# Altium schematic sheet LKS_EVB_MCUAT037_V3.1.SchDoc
size 203 x 203 mm; DocumentNumber: 1; SheetNumber: 1; SheetTotal: 1
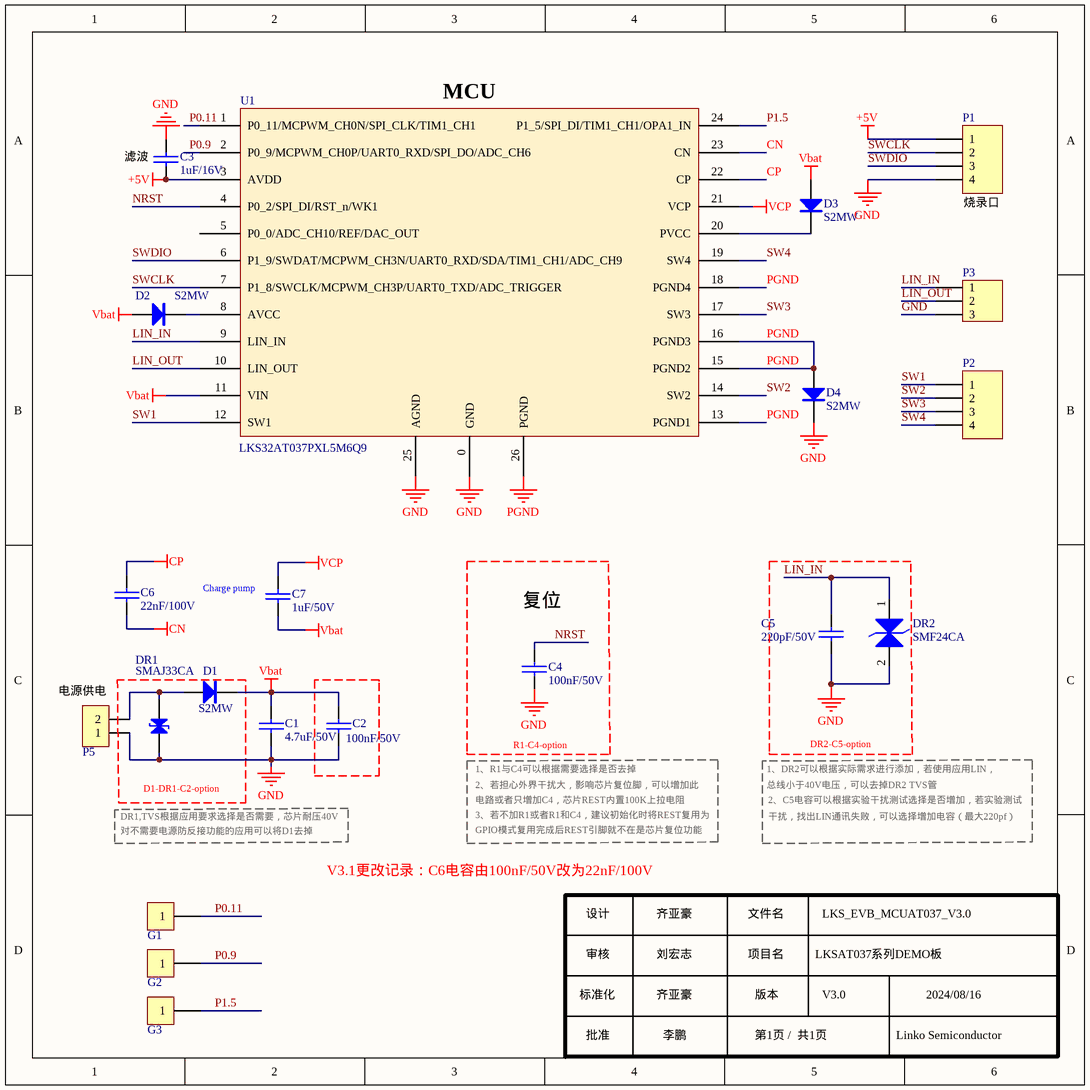
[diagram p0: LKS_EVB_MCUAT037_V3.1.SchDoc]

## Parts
C1  4.7uF/50V  [0805C]
C2  100nF/50V  [0603C]
C3  1uF/16V  [0603C]
C4  100nF/50V  [0603C]
C5  220pF/50V  [0603C]
C6  22nF/100V  [0603C]
C7  1uF/50V  [0603C]
D1  S2MW  [SOD-123]
D2  S2MW  [SOD-123]
D3  S2MW  [SOD-123]
D4  S2MW  [SOD-123]
DR1  SMAJ33CA  [SMB]
DR2  SMF24CA  [SOD-123F]
G1  PAD1.2  [TP-40]  (value not drawn)
G2  PAD1.2  [TP-40]  (value not drawn)
G3  PAD1.2  [TP-40]  (value not drawn)
P1  Header 4  [HDR 1X4]  (value not drawn)
P2  HDR-1X4  [HDR 1X4]  (value not drawn)
P3  1X3  [HDR 1X3]  (value not drawn)
P5  B2P-VH(LF)(SN)  [HDR 1X2]  (value not drawn)
U1  LKS32AT037PXL5M6Q9  [QFN24-0.55mm]

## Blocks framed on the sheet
复位: C4

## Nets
+5V: C3.2 P1.1 U1.3(AVDD)
CN: C6.2 U1.23(CN)
CP: C6.1 U1.22(CP)
GND: C1.2 C2.2 C3.1 C4.2 C5.2 D4.2(K) DR1.2(K) DR2.2(K) P1.4 P3.3 P5.1 U1.0(GND) U1.25(AGND)
PGND: D4.1(A) U1.13(PGND1) U1.15(PGND2) U1.16(PGND3) U1.18(PGND4) U1.26(PGND)
Vbat: C1.1 C2.1 C7.2 D1.2(K) D2.1(A) D3.1(A) U1.11(VIN)
VCP: C7.1 U1.21(VCP)
LIN_IN: C5.1 DR2.1(A) P3.1 U1.9(LIN_IN)
LIN_OUT: P3.2 U1.10(LIN_OUT)
NRST: C4.1 U1.4(P0_2/SPI_DI/RST_n/WK1)
P0.9: G2.1 U1.2(P0_9/MCPWM_CH0P/UART0_RXD/SPI_DO/ADC_CH6)
P0.11: G1.1 U1.1(P0_11/MCPWM_CH0N/SPI_CLK/TIM1_CH1)
P1.5: G3.1 U1.24(P1_5/SPI_DI/TIM1_CH1/OPA1_IN)
SW1: P2.1 U1.12(SW1)
SW2: P2.2 U1.14(SW2)
SW3: P2.3 U1.17(SW3)
SW4: P2.4 U1.19(SW4)
SWCLK: P1.2 U1.7(P1_8/SWCLK/MCPWM_CH3P/UART0_TXD/ADC_TRIGGER)
SWDIO: P1.3 U1.6(P1_9/SWDAT/MCPWM_CH3N/UART0_RXD/SDA/TIM1_CH1/ADC_CH9)
NetD1_1: D1.1(A) DR1.1(A) P5.2
NetD2_2: D2.2(K) U1.8(AVCC)
NetD3_2: D3.2(K) U1.20(PVCC)

Not connected (* = marked no-connect by the designer): U1 5(P0_0/ADC_CH10/REF/DAC_OUT)

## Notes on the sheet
- (near U1) MCU
- (near C3) 滤波
- (near P1) 烧录口
- (near C7) Charge pump
- (near P5) 电源供电
- 1、R1与C4可以根据需要选择是否去掉
- R1-C4-option
- 1、DR2可以根据实际需求进行添加，若使用应用LIN，
- DR2-C5-option
- 对不需要电源防反接功能的应用可以将D1去掉
- DR1,TVS根据应用要求选择是否需要，芯片耐压40V
- D1-DR1-C2-option
- 2、若担心外界干扰大，影响芯片复位脚，可以增加此
- 电路或者只增加C4，芯片REST内置100K上拉电阻
- 3、若不加R1或者R1和C4，建议初始化时将REST复用为
- GPIO模式复用完成后REST引脚就不在是芯片复位功能
- 总线小于40V电压，可以去掉DR2 TVS管
- 2、C5电容可以根据实验干扰测试选择是否增加，若实验测试
- 干扰，找出LIN通讯失败，可以选择增加电容（最大220pf）
- V3.1更改记录：C6电容由100nF/50V改为22nF/100V
- 设计
- 审核
- 齐亚豪
- 刘宏志
- 文件名
- 项目名
- LKSAT037系列DEMO板
- LKS_EVB_MCUAT037_V3.0
- 标准化
- 批准
- 李鹏
- 版本
- 第1页 /  共1页
- V3.0
- Linko Semiconductor
- 2024/08/16

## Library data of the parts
C1 C2 C5-C7 = Capacitor: Capacitor --贴片电容
C3 C4 = C: Capacitor
D1-D4 = 1N4148: 高速开关二极管; 版权归属: 源创客
DR1 = DR: 瞬态电压抑制二极管   极性：双向 反向截止电压(Vrwm)：24V 击穿电压：26.7V 反向漏电流(Ir)：1uA 峰值脉冲电流(Ipp)@10/1000μs：15.5A 最大钳位电压：38.9V TVS瞬态抑制二极管@10/1000μs：11.3A 最大钳位电压：53.3V; 钳位电压: 24; 击穿电压: 26.7
DR2 = TVS 双向: JLC-C5333993
G1-G3 = PAD1.2: 焊盘
P1 P2 = Header 4: Header, 4-Pin
P3 = 1X3: 单排针
P5 = Header 2: 2P接插件; 版权归属: 源创客
U1 = LKS32AT037PXL5M6Q9: 芯片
